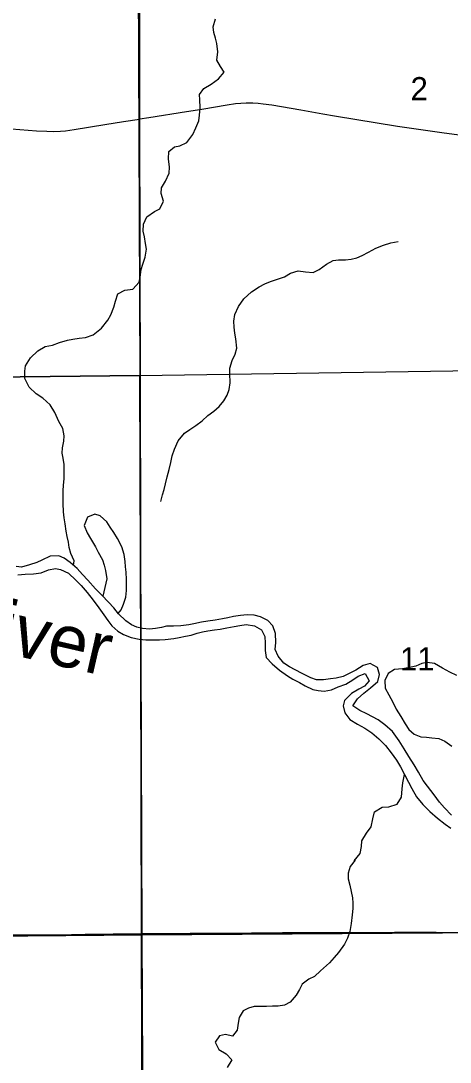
# Model space of a CAD drawing. Extents: x 0 to 34, y 0 to 22.
# Drawn here: x 3.216 to 3.99, y 16.037 to 17.915 of the extents above; entities that cross this region are included whole.
import ezdxf

# ---------------------------------------------------------------- set-up
doc = ezdxf.new("R2010")
doc.units = 0
for name, color, linetype in [('Default', 7, 'Continuous'), ('GM_X_Major_River', 7, 'Continuous'), ('GM_X_Major_River_Text', 7, 'Continuous'), ('GM_X_Minor_Lake', 7, 'Continuous'), ('GM_X_Minor_River', 7, 'Continuous'), ('GM_X_Section', 7, 'Continuous'), ('GM_X_Section_Text', 7, 'Continuous'), ('GM_X_State_Route', 7, 'Continuous'), ('GM_X_Township_Road', 7, 'Continuous')]:
    doc.layers.add(name, color=color, linetype=linetype)

msp = doc.modelspace()

# ---------------------------------------------------------------- linework, layer by layer
at = {"layer": 'Default'}
for points in [[(3.4301, 18.2744), (3.4297, 17.7382), (3.4335, 16.269), (3.4355, 15.6642)], [(3.4355, 15.6642), (3.4335, 16.269), (3.4297, 17.7382), (3.4301, 18.2744)]]:
    msp.add_lwpolyline(points, dxfattribs=at)
at = {"layer": 'GM_X_Major_River'}
for points in [[(3.9921, 16.4823), (3.9797, 16.4953), (3.971, 16.5056), (3.9612, 16.5185), (3.9491, 16.5342), (3.9416, 16.5444), (3.9326, 16.5597), (3.925, 16.5726), (3.9156, 16.5882), (3.9073, 16.6019), (3.8979, 16.6164), (3.8862, 16.6332), (3.8723, 16.645), (3.8602, 16.6538), (3.8499, 16.6595), (3.8397, 16.6649), (3.8272, 16.6706), (3.8144, 16.6791), (3.8228, 16.6919), (3.8342, 16.7021), (3.8464, 16.7116), (3.8593, 16.7229), (3.8628, 16.7361), (3.8587, 16.7483), (3.8458, 16.7556), (3.8329, 16.7522), (3.82, 16.7439), (3.807, 16.7368), (3.7968, 16.7323), (3.7846, 16.7293), (3.774, 16.7278), (3.7618, 16.7264), (3.7489, 16.7261), (3.7387, 16.7299), (3.7232, 16.7376), (3.7103, 16.7445), (3.7005, 16.7498), (3.6903, 16.7563), (3.6801, 16.7689), (3.6748, 16.7807), (3.676, 16.7936), (3.6754, 16.8096), (3.6705, 16.8236), (3.6614, 16.8335), (3.6482, 16.8397), (3.6364, 16.8428), (3.6243, 16.8432), (3.6118, 16.8421), (3.5992, 16.8403), (3.5894, 16.8381), (3.5795, 16.8362), (3.5662, 16.834), (3.5533, 16.8322), (3.5419, 16.8299), (3.5282, 16.827), (3.5187, 16.8251), (3.5047, 16.8237), (3.491, 16.823), (3.4789, 16.823), (3.4694, 16.8208), (3.4588, 16.819), (3.4481, 16.8175), (3.4352, 16.8187), (3.4254, 16.821), (3.4155, 16.8256), (3.4053, 16.8329), (3.3921, 16.8451), (3.3834, 16.8558), (3.374, 16.8664), (3.3619, 16.8786), (3.3506, 16.8905), (3.3366, 16.9057), (3.3272, 16.916), (3.3174, 16.9267), (3.3049, 16.9381), (3.2943, 16.9454), (3.2845, 16.9496), (3.2689, 16.9493), (3.2541, 16.9418), (3.2446, 16.9381), (3.2316, 16.9336), (3.2172, 16.9295), (3.2077, 16.9303)], [(3.2107, 16.9158), (3.2236, 16.9165), (3.2388, 16.9176), (3.2525, 16.9194), (3.2658, 16.9243), (3.2783, 16.9269), (3.2878, 16.9249), (3.3018, 16.9184), (3.315, 16.9058), (3.3248, 16.8963), (3.3354, 16.8837), (3.3463, 16.8696), (3.3569, 16.8559), (3.3659, 16.8433), (3.3731, 16.833), (3.3802, 16.8235), (3.3908, 16.814), (3.401, 16.8082), (3.4147, 16.8025), (3.4291, 16.7997), (3.4412, 16.7985), (3.4564, 16.7985), (3.4662, 16.7984), (3.4765, 16.7988), (3.4917, 16.801), (3.5016, 16.8024), (3.5126, 16.8047), (3.5228, 16.8069), (3.5338, 16.8106), (3.5437, 16.8129), (3.5532, 16.8147), (3.5654, 16.8162), (3.5756, 16.8176), (3.5874, 16.8199), (3.6007, 16.8221), (3.6109, 16.8243), (3.6223, 16.8258), (3.6371, 16.8238), (3.6496, 16.8165), (3.656, 16.8043), (3.6567, 16.7926), (3.6566, 16.7793), (3.6585, 16.7667), (3.669, 16.7549), (3.6823, 16.7435), (3.6966, 16.7335), (3.7065, 16.7274), (3.7186, 16.7213), (3.7284, 16.7155), (3.7424, 16.709), (3.7519, 16.7067), (3.7629, 16.7059), (3.7758, 16.7081), (3.7883, 16.7134), (3.8017, 16.7186), (3.8146, 16.7261), (3.8241, 16.7325), (3.837, 16.7374), (3.8442, 16.7245), (3.8354, 16.7146), (3.8251, 16.7094), (3.8122, 16.7018), (3.7996, 16.689), (3.7969, 16.6795), (3.8003, 16.6666), (3.8089, 16.6544), (3.8229, 16.646), (3.8362, 16.6391), (3.8487, 16.6307), (3.8611, 16.6196), (3.8732, 16.6078), (3.8838, 16.5948), (3.8932, 16.5815), (3.9003, 16.5693), (3.9146, 16.5419), (3.9206, 16.5301), (3.9293, 16.5153), (3.941, 16.5012), (3.9535, 16.4886), (3.9674, 16.4764), (3.9811, 16.4661), (3.9913, 16.4584)]]:
    msp.add_lwpolyline(points, dxfattribs=at)
at = {"layer": 'GM_X_Minor_Lake'}
msp.add_lwpolyline([(4.0017, 16.7343), (3.9896, 16.7401), (3.9763, 16.7474), (3.9616, 16.7554), (3.9483, 16.7577), (3.9388, 16.7559), (3.9282, 16.751), (3.9141, 16.7477), (3.9038, 16.7462), (3.8898, 16.7447), (3.8784, 16.7376), (3.8723, 16.7251), (3.8729, 16.711), (3.8797, 16.6989), (3.8865, 16.6859), (3.8929, 16.673), (3.9008, 16.66), (3.9091, 16.6471), (3.9155, 16.6364), (3.9253, 16.628), (3.9374, 16.6234), (3.9473, 16.6226), (3.9568, 16.6218), (3.9693, 16.6206), (3.9806, 16.6156), (3.9927, 16.6065)], dxfattribs=at)
at = {"layer": 'GM_X_Minor_River'}
for points in [[(3.3108, 16.9327), (3.3121, 16.9408), (3.3061, 16.9541), (3.3031, 16.9647), (3.3017, 16.9742), (3.2998, 16.9849), (3.298, 16.9944), (3.2957, 17.0073), (3.2939, 17.0183), (3.2928, 17.0293), (3.2921, 17.0445), (3.2922, 17.0673), (3.293, 17.0771), (3.2939, 17.0885), (3.2943, 17.1018), (3.294, 17.1143), (3.2925, 17.1257), (3.2907, 17.1352), (3.2911, 17.1447), (3.2938, 17.1568), (3.2942, 17.1663), (3.292, 17.1796), (3.2845, 17.1922), (3.2774, 17.2085), (3.2687, 17.2219), (3.2555, 17.2341), (3.2434, 17.2421), (3.2309, 17.2543), (3.2234, 17.2699), (3.2231, 17.2832), (3.2246, 17.2927), (3.2334, 17.3071), (3.2464, 17.3195), (3.2601, 17.3271), (3.273, 17.33), (3.2855, 17.3345), (3.3, 17.3386), (3.3095, 17.3409), (3.3212, 17.3423), (3.3326, 17.3438), (3.3467, 17.3483), (3.3616, 17.3607), (3.3726, 17.3747), (3.378, 17.3846), (3.3837, 17.3986), (3.3868, 17.4092), (3.3911, 17.4225), (3.4036, 17.4289), (3.4177, 17.4311), (3.4291, 17.4432), (3.4314, 17.4526), (3.433, 17.4663), (3.4357, 17.4758), (3.4399, 17.4887), (3.4427, 17.5027), (3.4408, 17.5129), (3.439, 17.5251), (3.4368, 17.5354), (3.4372, 17.5483), (3.4433, 17.5615), (3.457, 17.5706), (3.4669, 17.5758), (3.4731, 17.5895), (3.4693, 17.6032), (3.4694, 17.6134), (3.477, 17.6259), (3.4832, 17.6399), (3.4843, 17.6509), (3.4821, 17.6657), (3.4826, 17.679), (3.4929, 17.6877), (3.5027, 17.6892), (3.5153, 17.6956), (3.5264, 17.7099), (3.5317, 17.7217), (3.5367, 17.7345), (3.5383, 17.7444), (3.5391, 17.7585), (3.5388, 17.7725), (3.5381, 17.782), (3.5457, 17.793), (3.5591, 17.8005), (3.5724, 17.8099), (3.5827, 17.822), (3.5759, 17.8323), (3.5691, 17.8441), (3.5711, 17.8589), (3.5693, 17.8741), (3.5667, 17.8836), (3.564, 17.8935), (3.563, 17.9037), (3.5668, 17.9181)], [(3.4686, 17.0478), (3.4717, 17.0599), (3.4744, 17.0694), (3.4767, 17.0797), (3.4798, 17.0925), (3.4833, 17.1054), (3.4864, 17.1179), (3.4891, 17.1305), (3.4929, 17.1422), (3.4998, 17.1574), (3.5109, 17.171), (3.5208, 17.1774), (3.5315, 17.1849), (3.5429, 17.1936), (3.5532, 17.203), (3.5642, 17.2106), (3.5737, 17.2189), (3.5817, 17.2295), (3.5879, 17.2397), (3.5913, 17.2499), (3.5937, 17.2621), (3.593, 17.2788), (3.5927, 17.2882), (3.5973, 17.3023), (3.6026, 17.3136), (3.6057, 17.3246), (3.6039, 17.341), (3.6017, 17.3512), (3.6006, 17.3622), (3.5999, 17.3729), (3.6018, 17.385), (3.6084, 17.3994), (3.6183, 17.4134), (3.632, 17.4259), (3.6457, 17.4353), (3.6556, 17.4405), (3.6662, 17.4447), (3.6807, 17.4492), (3.6913, 17.4533), (3.702, 17.4597), (3.7157, 17.4638), (3.7293, 17.4622), (3.743, 17.461), (3.754, 17.4663), (3.7669, 17.4761), (3.7791, 17.4825), (3.7886, 17.4836), (3.8011, 17.4835), (3.8114, 17.485), (3.8216, 17.4876), (3.8315, 17.4917), (3.8426, 17.4977), (3.8562, 17.5045), (3.8699, 17.5101), (3.8828, 17.5142), (3.8961, 17.5168)], [(3.3915, 16.8458), (3.3971, 16.8527), (3.4013, 16.8625), (3.4055, 16.8754), (3.4067, 16.8872), (3.4064, 16.897), (3.4064, 16.9073), (3.4057, 16.9206), (3.405, 16.9301), (3.4039, 16.9396), (3.4025, 16.9521), (3.3984, 16.9662), (3.3905, 16.9814), (3.3837, 16.992), (3.3773, 17.0016), (3.3709, 17.0111), (3.3592, 17.0221), (3.3493, 17.0248), (3.3364, 17.0196), (3.3303, 17.0048), (3.3355, 16.9911), (3.3415, 16.9809), (3.3509, 16.966), (3.3555, 16.9565), (3.363, 16.9428), (3.366, 16.9329), (3.3686, 16.9234), (3.3708, 16.9086), (3.3638, 16.8768)], [(3.817, 16.3996), (3.8277, 16.4128), (3.8301, 16.4257), (3.8306, 16.4356), (3.8391, 16.4495), (3.8475, 16.4612), (3.8503, 16.4752), (3.8538, 16.4881), (3.8672, 16.4963), (3.8797, 16.4973), (3.8942, 16.5021), (3.9022, 16.5146), (3.9035, 16.5293), (3.9044, 16.5407), (3.9076, 16.5554)], [(3.8189, 16.4011), (3.8095, 16.3897), (3.8064, 16.3776), (3.8064, 16.3673), (3.8091, 16.3556), (3.8113, 16.3442), (3.814, 16.3328), (3.8147, 16.3233), (3.8143, 16.3139), (3.8136, 16.3021), (3.8117, 16.2865), (3.809, 16.2725), (3.8048, 16.2604), (3.7995, 16.2494), (3.7885, 16.2346), (3.7809, 16.2251), (3.7722, 16.2156), (3.7563, 16.2012), (3.7453, 16.1913), (3.7354, 16.186), (3.7229, 16.1773), (3.7184, 16.1678), (3.7123, 16.1576), (3.7017, 16.1451), (3.6914, 16.1397), (3.6797, 16.1378), (3.6695, 16.1375), (3.6588, 16.1367), (3.6486, 16.1371), (3.6369, 16.1367), (3.6262, 16.134), (3.6168, 16.1291), (3.6095, 16.1174), (3.6076, 16.1067), (3.6061, 16.0942), (3.5974, 16.0836), (3.5849, 16.0862), (3.5743, 16.0843), (3.5663, 16.0726), (3.5731, 16.0593), (3.5864, 16.0517), (3.5962, 16.0407), (3.5879, 16.0267)]]:
    msp.add_lwpolyline(points, dxfattribs=at)
at = {"layer": 'GM_X_Section'}
for points in [[(2.4116, 18.261), (2.4434, 18.2628), (3.4263, 18.2757), (3.4308, 17.2748), (2.406, 17.2639)], [(4.3145, 18.2784), (3.4536, 18.2761), (3.4263, 18.2757), (3.4308, 17.2748), (4.4385, 17.29), (4.4398, 17.662), (4.3145, 17.662)], [(3.4308, 17.2748), (4.4385, 17.29), (4.4273, 16.2727), (3.434, 16.2663)], [(3.4308, 17.2748), (3.434, 16.2663), (2.4062, 16.2575), (2.4062, 16.2613), (2.406, 17.2639)], [(2.4062, 16.2575), (3.434, 16.2663), (3.4363, 15.7808), (3.4219, 15.2567), (2.4044, 15.2506)], [(3.434, 16.2663), (4.4273, 16.2727), (4.4235, 15.2608), (3.4219, 15.2567), (3.4363, 15.7808)]]:
    msp.add_lwpolyline(points, close=True, dxfattribs=at)
at = {"layer": 'GM_X_State_Route'}
for points in [[(3.4308, 17.7378), (3.447, 17.7403), (3.5144, 17.7511), (3.5421, 17.7555), (3.588, 17.7632), (3.6033, 17.7654), (3.6126, 17.7663), (3.622, 17.7667), (3.6344, 17.7667), (3.6438, 17.7663), (3.6531, 17.7653), (3.6685, 17.7631), (3.7206, 17.7543), (3.7603, 17.7471), (3.7817, 17.7432), (3.8951, 17.7251), (3.9751, 17.7136), (4.1045, 17.6961), (4.1721, 17.6862), (4.2671, 17.6703), (4.3145, 17.6622)], [(2.8645, 17.7422), (2.8754, 17.7432), (2.8817, 17.7439), (2.891, 17.744), (2.9035, 17.7435), (2.9468, 17.7398), (3.0118, 17.7344), (3.1388, 17.7251), (3.2441, 17.7166), (3.2627, 17.7156), (3.2751, 17.7154), (3.2875, 17.7158), (3.2967, 17.7166), (3.312, 17.7187), (3.3672, 17.7277), (3.401, 17.7333), (3.4299, 17.7377), (3.4308, 17.7378)]]:
    msp.add_lwpolyline(points, dxfattribs=at)
at = {"layer": 'GM_X_Township_Road'}
msp.add_line((3.3824, 16.2678), (3.4337, 16.2684), dxfattribs=at)
for points in [[(2.4057, 16.2577), (2.4147, 16.2579), (2.454, 16.2585), (2.4851, 16.2588), (2.5224, 16.2589), (2.5317, 16.259), (2.5472, 16.2589), (2.5876, 16.2589), (2.5907, 16.2592), (2.6559, 16.2599), (2.7053, 16.2602), (2.7891, 16.2612), (2.8294, 16.2613), (2.8658, 16.262), (2.9593, 16.2638), (2.9997, 16.2643), (3.0432, 16.2646), (3.1239, 16.2652), (3.1705, 16.2659), (3.1985, 16.2662), (3.3072, 16.2671), (3.332, 16.2672), (3.3824, 16.2678)], [(3.4337, 16.2684), (3.4438, 16.2685), (3.5215, 16.269), (3.5584, 16.2694), (3.5894, 16.2695), (3.632, 16.2701), (3.6877, 16.2702), (3.7374, 16.2704), (3.7746, 16.2707), (3.8897, 16.2711), (3.9302, 16.2713), (3.965, 16.2709), (3.9923, 16.2705), (4.072, 16.2697), (4.077, 16.2696), (4.0828, 16.2691), (4.0899, 16.2671)]]:
    msp.add_lwpolyline(points, dxfattribs=at)

# ---------------------------------------------------------------- texts
at = {"layer": 'GM_X_Major_River_Text'}
msp.add_text('River', height=0.09473, rotation=347.0559, dxfattribs=at).set_placement((3.08, 16.7987))
at = {"layer": 'GM_X_Section_Text'}
for s, height, p in [('2', 0.0419, (3.9186, 17.7714)), ('11', 0.04186, (3.8994, 16.7432))]:
    msp.add_text(s, height=height, rotation=0, dxfattribs=at).set_placement(p)

doc.saveas('drawing.dxf')
